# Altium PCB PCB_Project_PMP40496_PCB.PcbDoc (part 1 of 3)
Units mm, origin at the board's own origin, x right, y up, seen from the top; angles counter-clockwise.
Board outline 140 x 100 mm, 4 copper layers (Top Layer, Signal Layer 1, Signal Layer 2, Bottom Layer), stack 1.565 mm thick; 186 components, 128 nets, 605 pads, 270 vias.
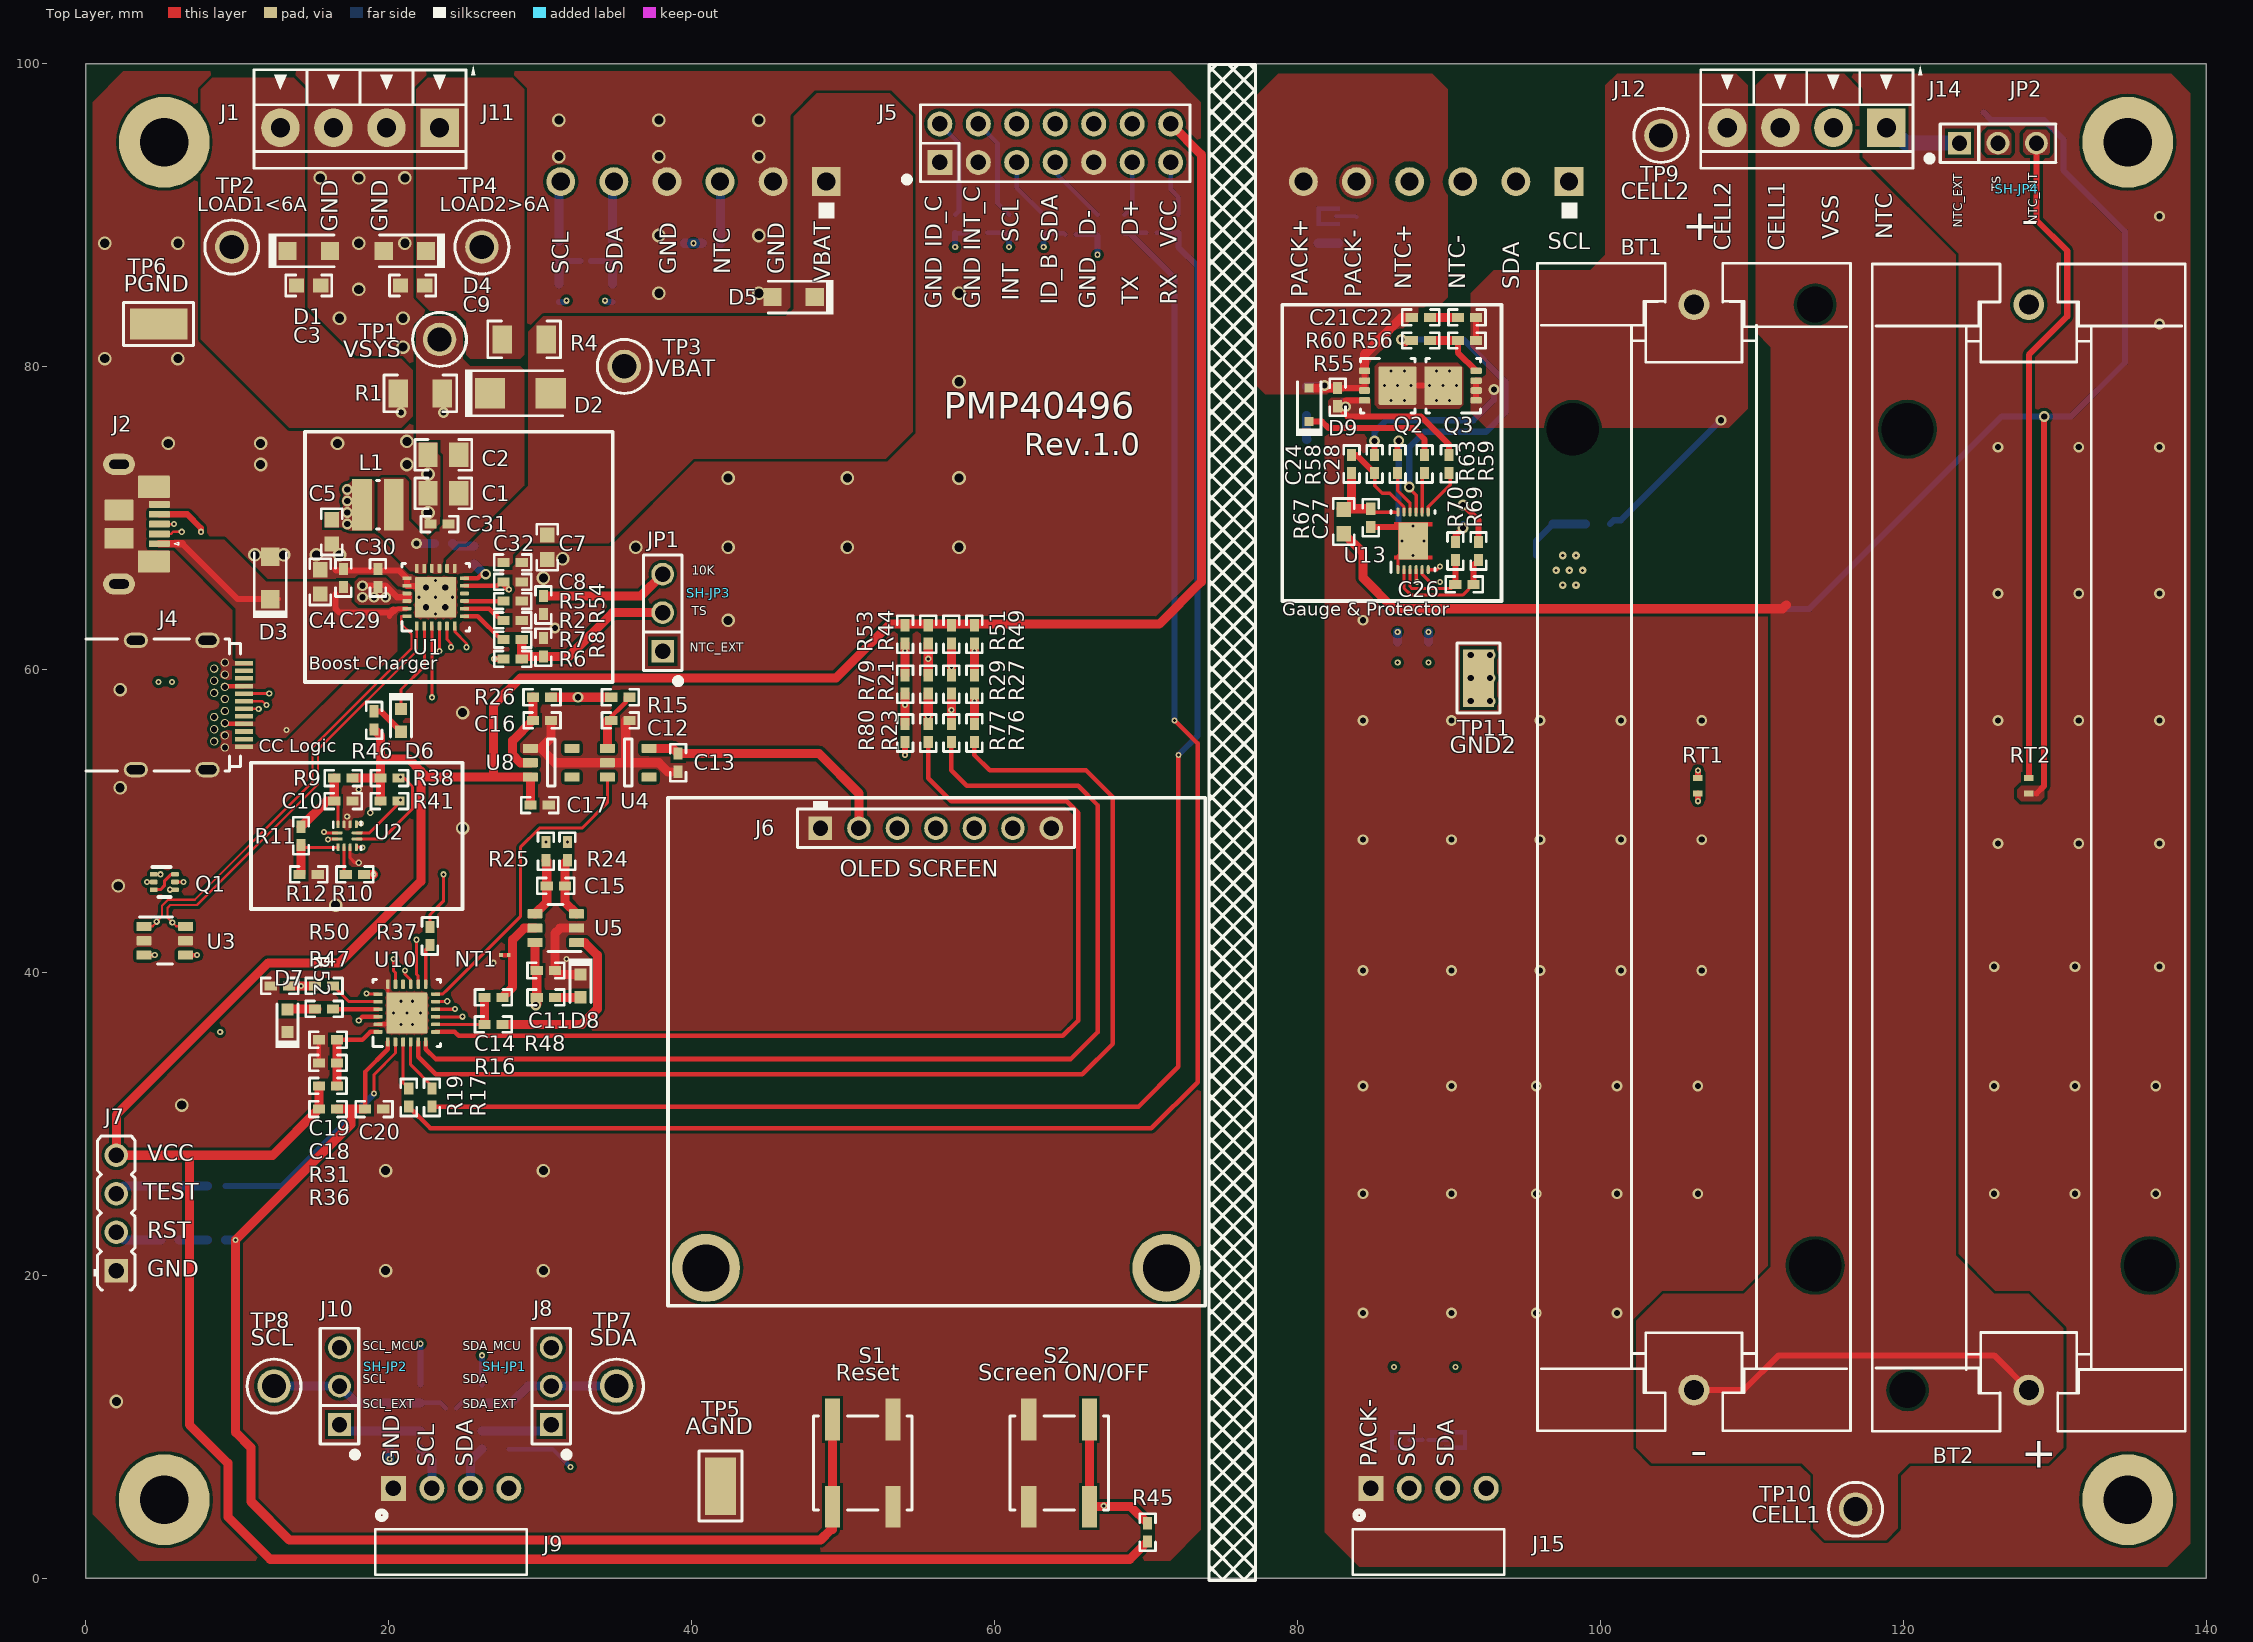
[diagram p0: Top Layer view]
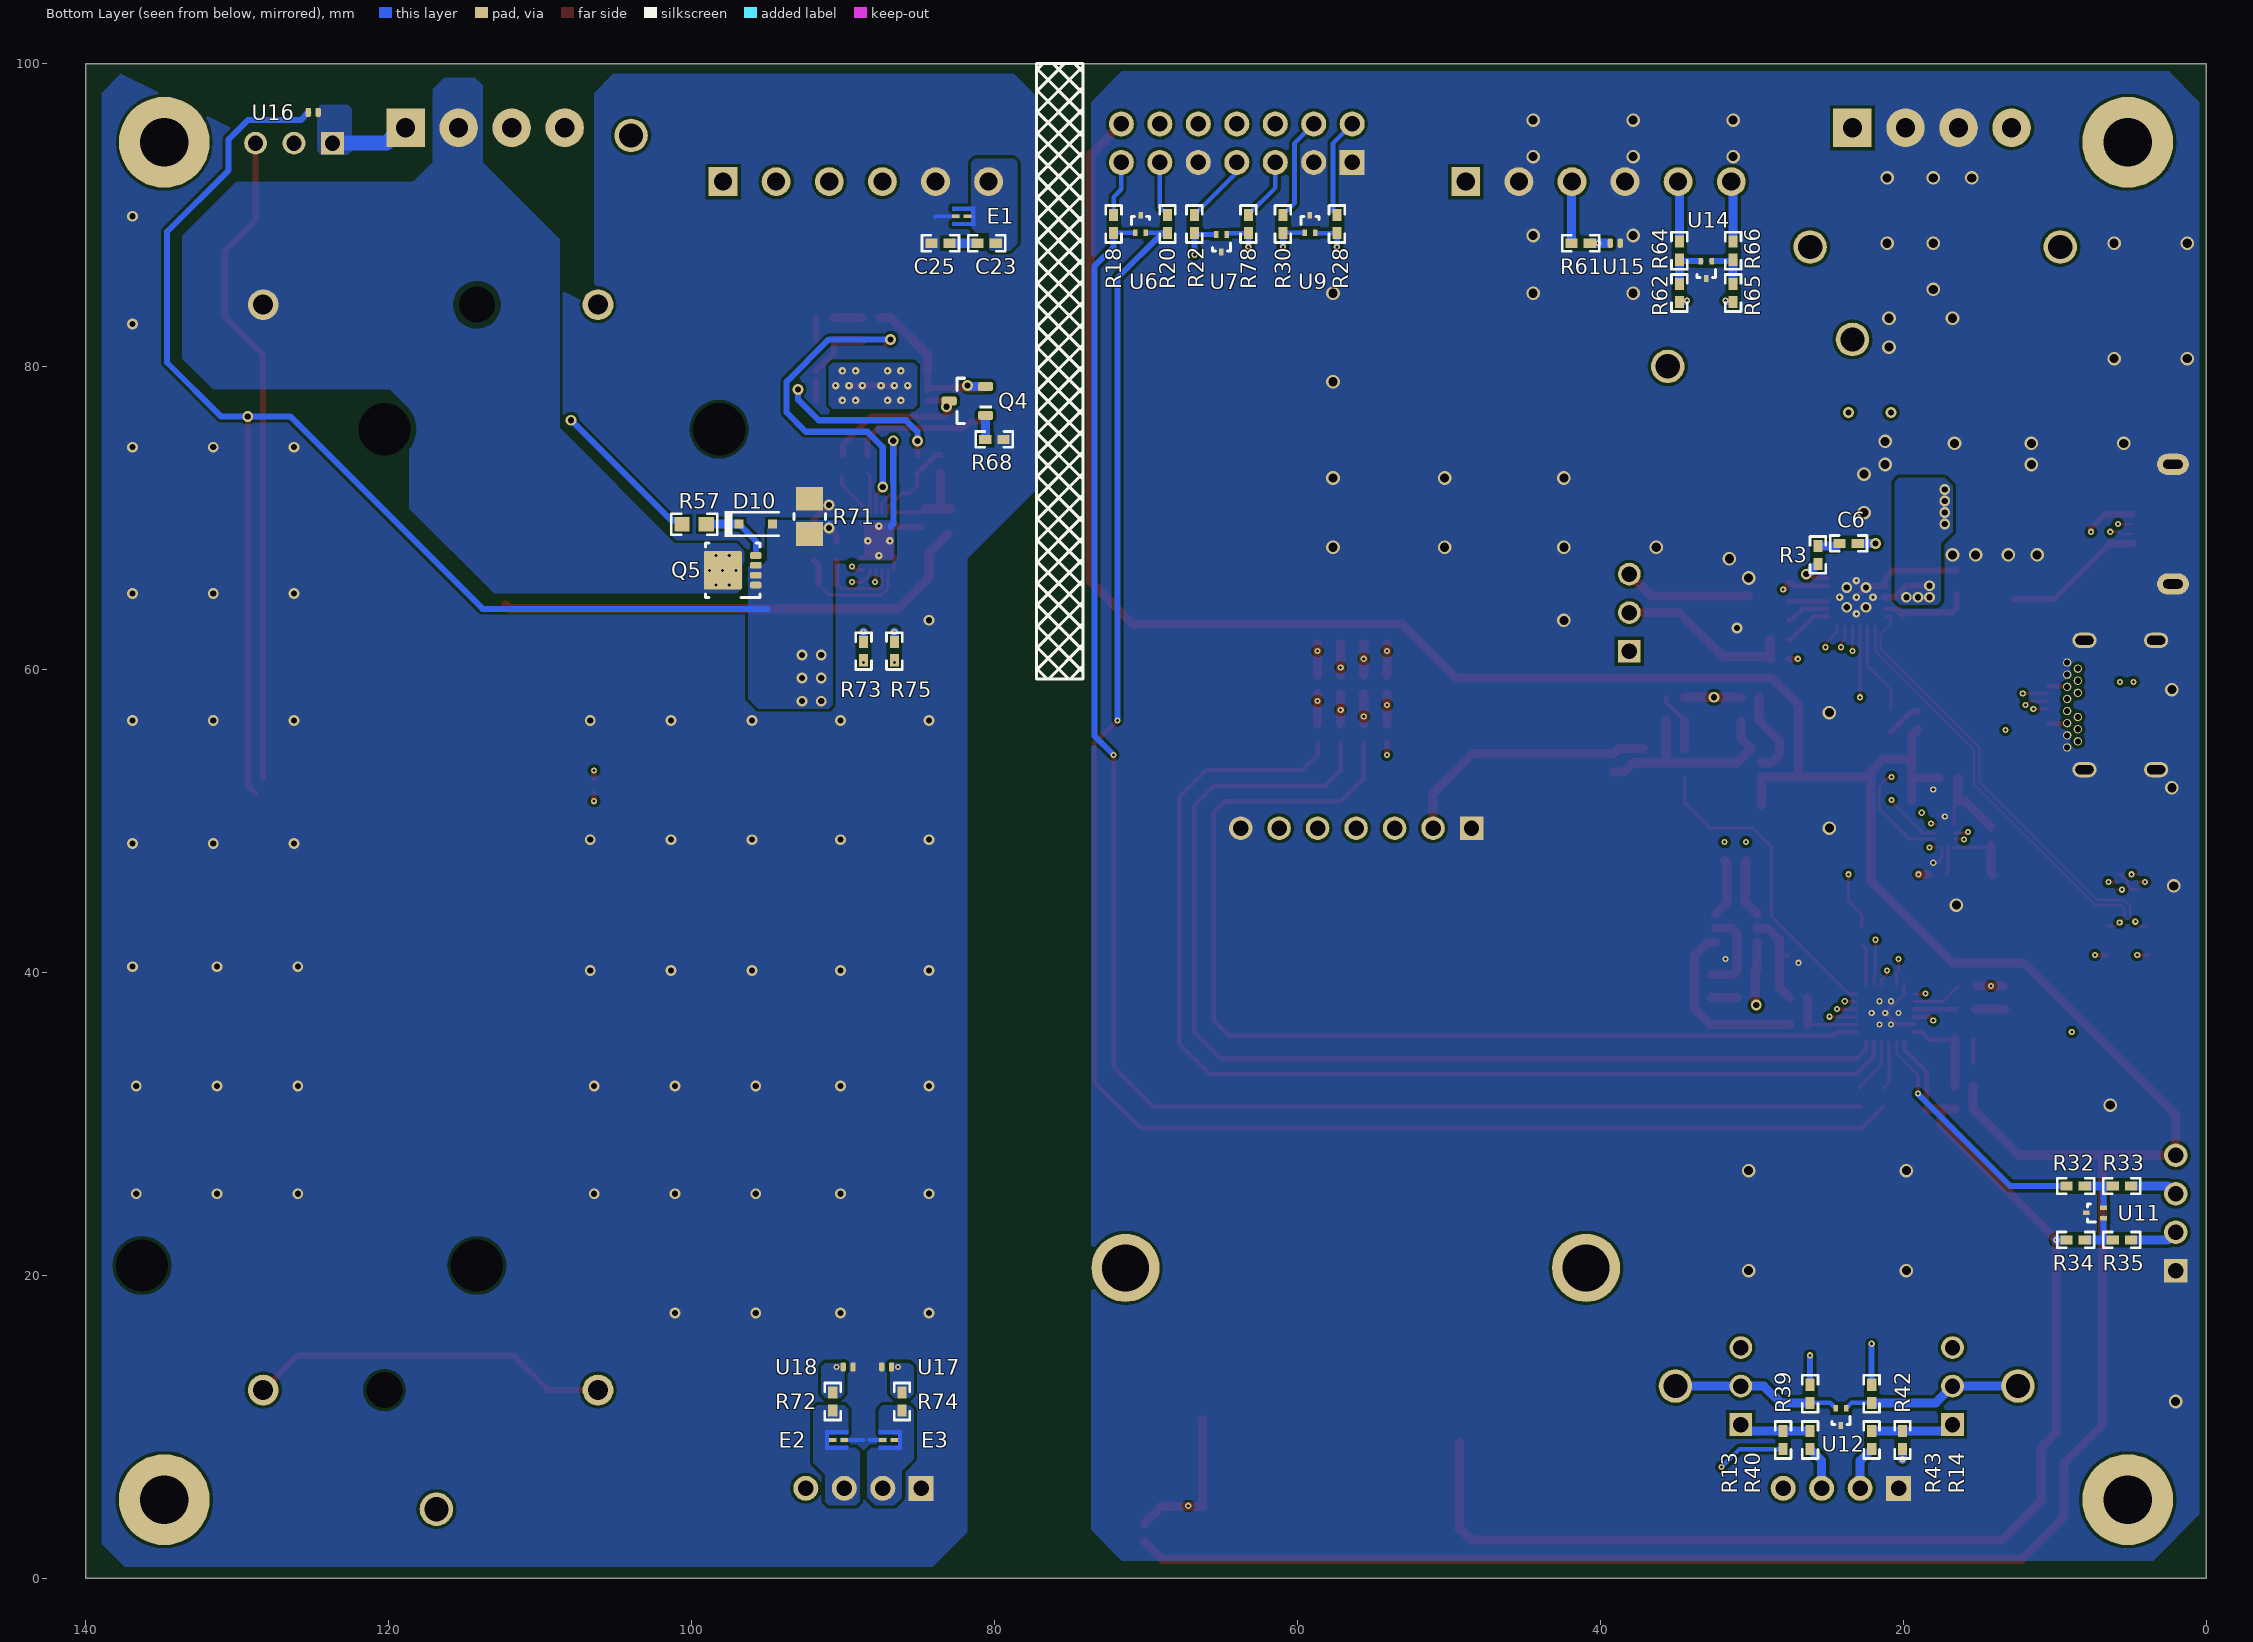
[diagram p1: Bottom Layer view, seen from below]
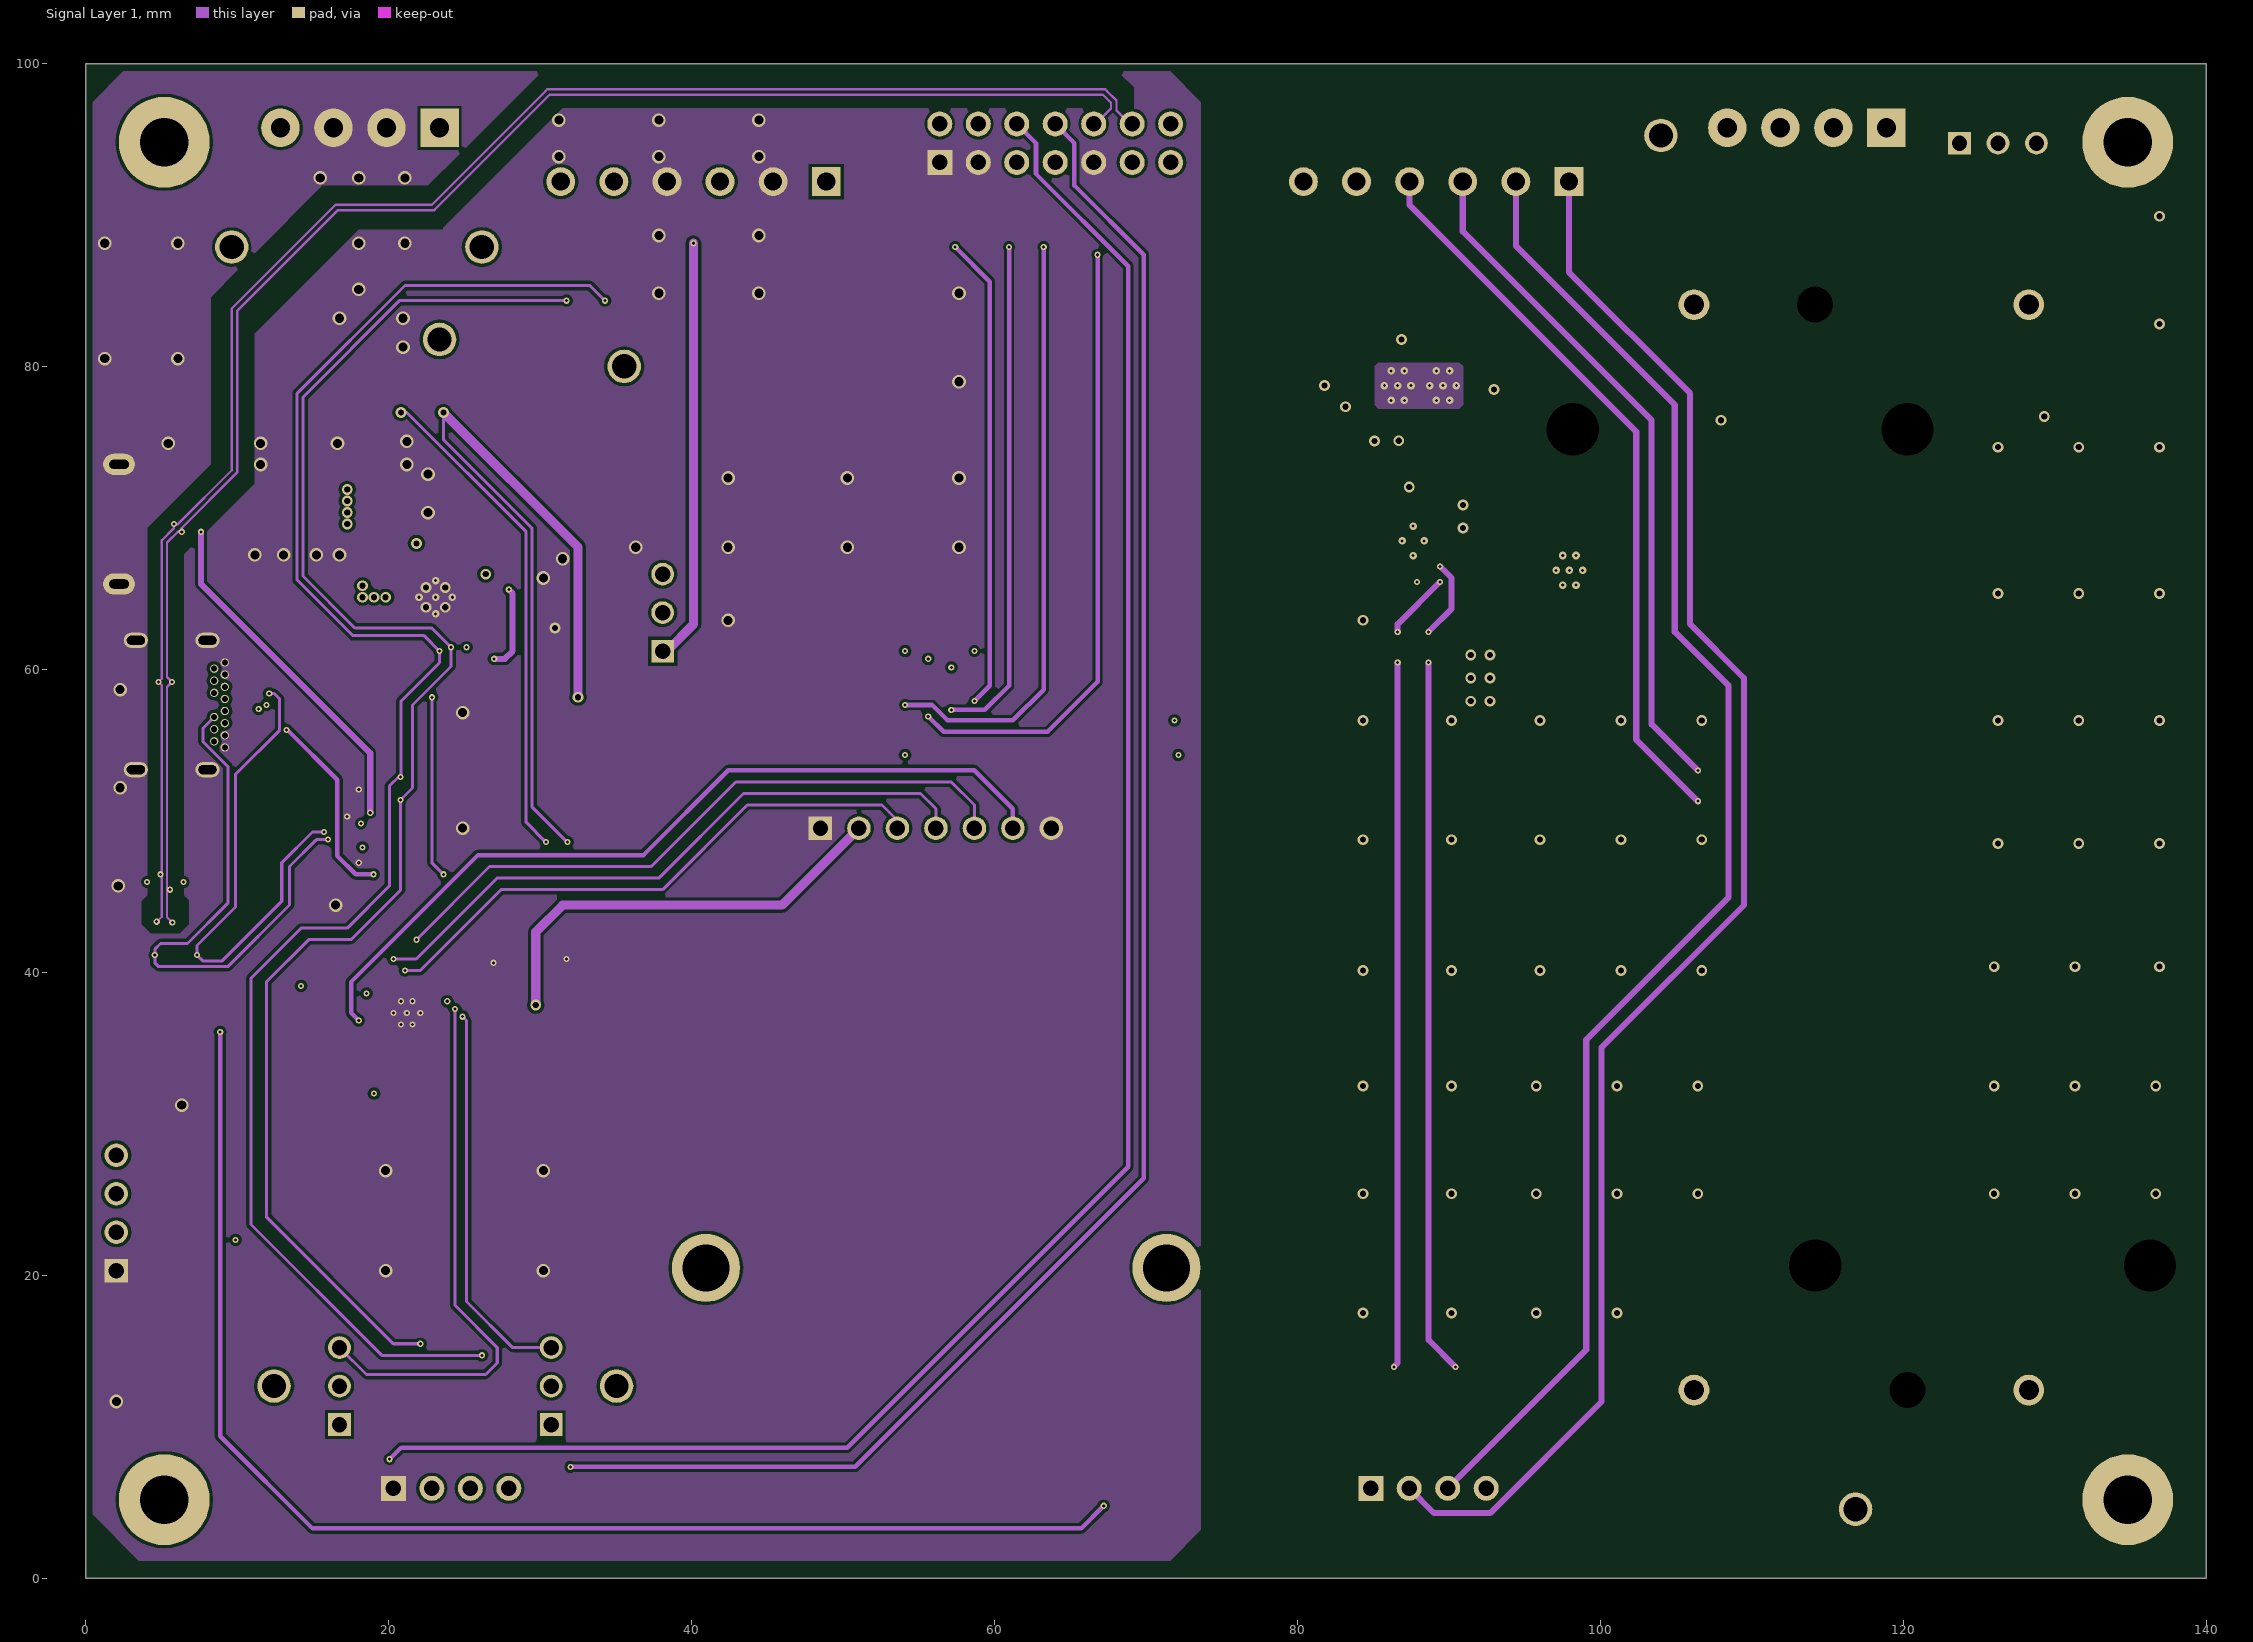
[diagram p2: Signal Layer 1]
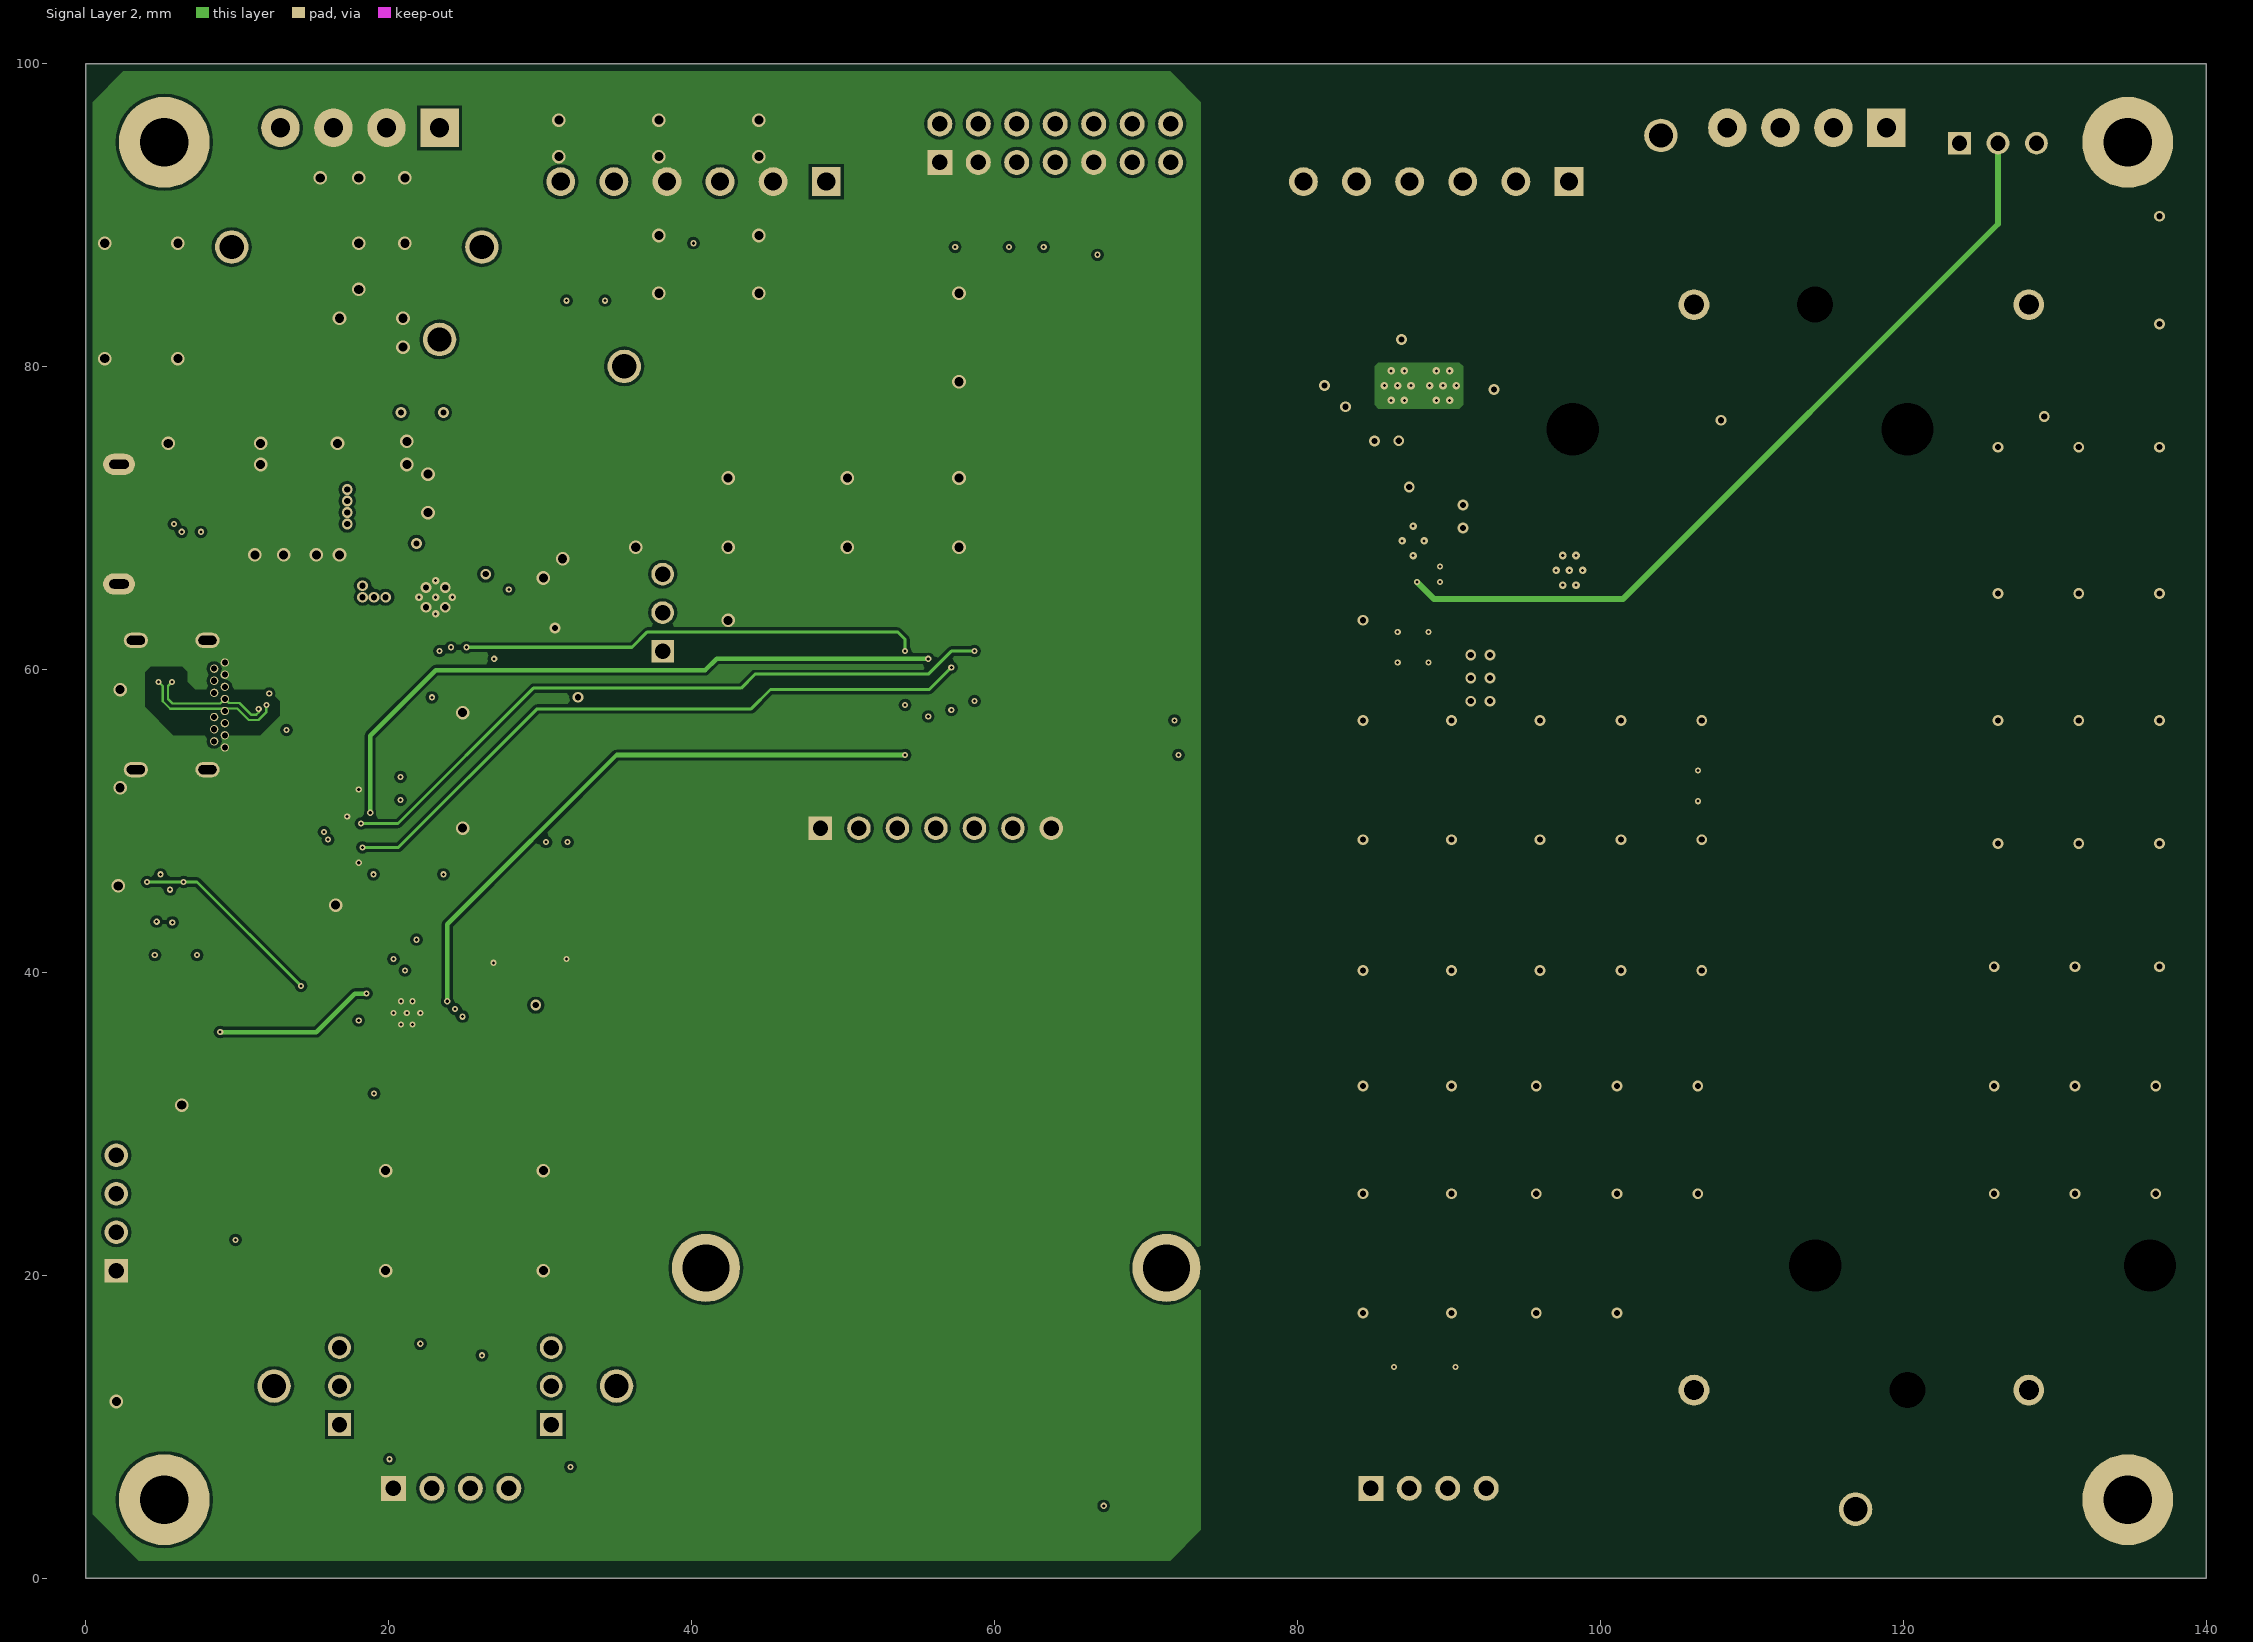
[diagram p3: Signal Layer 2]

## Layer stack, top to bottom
Top Solder: solder mask 0.0102, Solder Resist, Dk 3.5
Top Layer: signal copper 0.0356
Dielectric 1: prepreg 0.2032, FR-4, Dk 4.2
Signal Layer 1: signal copper 0.0356
Dielectric 2: core 1.016, FR-4, Dk 4.2
Signal Layer 2: signal copper 0.0356
Dielectric 3: prepreg 0.2032, FR-4, Dk 4.2
Bottom Layer: signal copper 0.0356
Bottom Solder: solder mask 0.0102, Solder Resist, Dk 3.5

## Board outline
0,0 140,0 140,100 0,100

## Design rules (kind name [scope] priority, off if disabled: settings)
AcuteAngle [All] p1: minimum=4.50000000000000E+0001 checktracksonly=FALSE
AssemblyTestPointUsage [All] p1: valid=2
Clearance Clearance_BoardEdge_MountingHoles [OnCopper and InComponentClass('Mounting Holes') vs IsKeepOut] p1: gap=1.016 ignorepadtopadclearanceinfootprint=FALSE except(0: Arc-Hole Track-Hole SMDPad-Hole THPad-Hole Via-Hole Fill-Hole Poly-Hole Region-Hole Text-Hole)
Clearance Clearance_BoardEdge_Poly [OnCopper and InPoly vs IsKeepOut] p2: gap=0.635 ignorepadtopadclearanceinfootprint=FALSE except(0: Arc-Hole Track-Hole SMDPad-Hole THPad-Hole Via-Hole Fill-Hole Poly-Hole Region-Hole Text-Hole)
Clearance Clearance_BoardEdge [OnCopper and Not InComponentClass('Logo') and not InComponentClass('FiducialMark') and not InRegion(1000,500,4000,800) and Not IsKeepout vs IsKeepOut] p3: gap=0.127 ignorepadtopadclearanceinfootprint=FALSE except(0: Arc-Hole Track-Hole SMDPad-Hole THPad-Hole Via-Hole Fill-Hole Poly-Hole Region-Hole Text-Hole)
Clearance Clearance_Poly [InPolygon] p4: gap=0.2 ignorepadtopadclearanceinfootprint=FALSE
Clearance [All] p5: gap=0.15 ignorepadtopadclearanceinfootprint=FALSE
ComponentClearance ComponentClearance_Logo [All] p1: gap=0.254 collisioncheckmode=3 verticalgap=0.254 showdistances=TRUE
ComponentClearance ComponentClearance_ScrewToNut [(HasFootprint('NY PMS 440 0025 PH')) vs (HasFootprint('Keystone_1902C'))] p2: gap=0.127 collisioncheckmode=3 verticalgap=0.254 showdistances=FALSE
ComponentClearance ComponentClearance_MountingHoles [InComponentClass('Mounting Holes')] p3: gap=0.254 collisioncheckmode=3 verticalgap=2540 showdistances=FALSE
ComponentClearance ComponentClearance_SmallPassives [HasFootprint('0201*') or HasFootprint('0402*') or HasFootprint('0508') or HasFootprint('0603*') or HasFootprint('0612') or HasFootprint('0805*') or HasFootprint('0815*') or HasFootprint('0830*') or HasFootprint('1206*') or HasFootprint('1210*') or HasFootprint('1808*') or HasFootprint('1812*') or HasFootprint('1825*') or HasFootprint('2010*') or HasFootprint('2220*') or HasFootprint('2225*') or HasFootprint('2512*') or HasFootprint('2728*') or HasFootprint('3518*') vs HasFootprint('0201*') or HasFootprint('0402*') or HasFootprint('0508') or HasFootprint('0603*') or HasFootprint('0612') or HasFootprint('0805*') or HasFootprint('0815*') or HasFootprint('0830*') or HasFootprint('1206*') or HasFootprint('1210*') or HasFootprint('1808*') or HasFootprint('1812*') or HasFootprint('1825*') or HasFootprint('2010*') or HasFootprint('2220*') or HasFootprint('2225*') or HasFootprint('2512*') or HasFootprint('2728*') or HasFootprint('3518*')] p4: gap=0.254 collisioncheckmode=3 verticalgap=0.254 showdistances=FALSE
ComponentClearance ComponentClearance_THtoSMT [IsThruComponent vs IsSMTComponent] p5: gap=0.254 collisioncheckmode=3 verticalgap=2540 showdistances=FALSE
ComponentClearance ComponentClearance_THtoTH [IsThruComponent vs IsThruComponent] p6: gap=0.254 collisioncheckmode=3 verticalgap=2540 showdistances=FALSE
ComponentClearance [All] p7: gap=0.254 collisioncheckmode=3 verticalgap=0.254 showdistances=FALSE
DiffPairsRouting DiffPair_90OMDiffPairsRouting [InDifferentialPair ('DATA')] p1: maxlimit=0.203 minlimit=0.203 mostfreqgap=0.203 toplayer_minwidth=0.152 toplayer_maxwidth=0.152 toplayer_prefwidth=0.152 midlayer1_minwidth=0.152 midlayer1_maxwidth=0.152 midlayer1_prefwidth=0.152 midlayer2_minwidth=0.152 midlayer2_maxwidth=0.152 midlayer2_prefwidth=0.152 bottomlayer_minwidth=0.152 bottomlayer_maxwidth=0.152 bottomlayer_prefwidth=0.152 maxuncoupledlength=25.4
DiffPairsRouting [All] p2: maxlimit=0.203 minlimit=0.203 mostfreqgap=0.203 toplayer_minwidth=0.152 toplayer_maxwidth=0.152 toplayer_prefwidth=0.152 midlayer1_minwidth=0.152 midlayer1_maxwidth=0.152 midlayer1_prefwidth=0.152 midlayer2_minwidth=0.152 midlayer2_maxwidth=0.152 midlayer2_prefwidth=0.152 bottomlayer_minwidth=0.152 bottomlayer_maxwidth=0.152 bottomlayer_prefwidth=0.152 maxuncoupledlength=25.4
FabricationTestPointUsage TestPointUsage [All] p1: valid=2 allowmultiple=FALSE
FabricationTestpoint Testpoint [All] p1: side=3 testpointundercomponent=TRUE minsize=1.016 maxsize=2.54 preferedsize=1.524 minholesize=0 maxholesize=1.016 preferedholesize=0.813 testpointgrid=0.025 allowsidetop=TRUE allowsidebottom=TRUE usegrid=TRUE gridtolerance=0
FanoutControl Fanout_LCC [IsLCC] p1: bgadir=Out bgaviamode=Centered fanoutstyle=Auto fanoutdirection=Alternating viagrid=0.025 // Fanout_LCC (Default Rule)
FanoutControl Fanout_BGA [IsBGA] p2: bgadir=Out bgaviamode=Centered fanoutstyle=Auto fanoutdirection=Alternating viagrid=0.025 // Fanout_BGA (Default Rule)
FanoutControl Fanout_Default [All] p4: bgadir=Out bgaviamode=Centered fanoutstyle=Auto fanoutdirection=Alternating viagrid=0.025 // Fanout_Default (Default Rule)
FanoutControl Fanout_Small [(CompPinCount < 5)] p5: bgadir=Out bgaviamode=Centered fanoutstyle=Auto fanoutdirection=OutThenIn viagrid=0.025 // Fanout_Small (Default Rule)
HoleSize [All] p1: absolutevalues=TRUE maxlimit=6.375 minlimit=0.152 maxpercent=80.000 minpercent=20.000
MatchedLengths DiffPair_90OMMatchedLengths [InDifferentialPair ('DATA')] p1: tolerance=25.4 checknetsindiffpair=FALSE checkdiffpairvsdiffpair=TRUE checkxsignals=TRUE checkothers=TRUE
MinimumAnnularRing [All] p1: minimumring=0.074
MinimumSolderMaskSliver MinimumSolderMaskSliver_Logo [InComponentClass('Logo') vs InComponentClass('Logo')] p1: minsoldermaskwidth=0.018
MinimumSolderMaskSliver [All] p2: minsoldermaskwidth=0
PlaneConnect [All] p1: planeconnectstyle=Direct reliefexpansion=0.254 reliefentries=4 reliefconductorwidth=0.254 reliefairgap=0.254
PolygonConnect [All] p1: connectstyle=Direct reliefconductorwidth=0.254 reliefentries=4 polygonreliefangle="90 Angle" airgapwidth=0.254
RoutingCorners [All] p1: cornerstyle=45-Degree minsetback=0.254 maxsetback=2.54
RoutingVias [All] p1: holewidth=0.406 width=0.864 viastyle="Through Hole" minholewidth=0.2 minwidth=0.406 maxholewidth=1.016 maxwidth=1.651
SMDToCorner [All] p1: distance=0
SilkToBoardRegionClearance [Not ((IsComment or IsDesignator) And (Hide <> 'False')) and not InRegion(1000,500,4000,800)] p1:
SilkToSilkClearance [All] p1: silktosilkclearance=0
SilkToSolderMaskClearance SilkscreenOverComponentPads [IsPad] p1: minsilkscreentomaskgap=0 clearancetoexposedcopper=TRUE
SolderMaskExpansion [All] p1: expansion=0.076
Width [All] p1: maxlimit=2.54 minlimit=0.152 preferedwidth=0.254 checkconnectedcopper=TRUE
14 further rules are at their usual default settings.

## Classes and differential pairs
component class Shunt: SH-JP1 SH-JP2 SH-JP3 SH-JP4
component class PCB_Project_PMP40496_BatteryPack: BT1 BT2 C21 C22 C23 C24 C25 C26 C27 C28 D9 D10 E1 E2 E3 J11 J12 J14 J15 JP1 JP2 Q2 Q3 Q4 Q5 R54 R55 R56 R57 R58 R59 R60 R61 R62 R63 R64 R65 R66 R67 R68 R69 R70 R71 R72 R73 R74 R75 RT1 RT2 SH-JP3 SH-JP4 TP9 TP10 TP11 U13 U14 U15 U16 U17 U18
component class Header: J5 J7 J8 J10 JP1 JP2
component class PCB_Project_PMP40496_BlankSheet: C1 C2 C3 C4 C5 C6 C7 C8 C9 C10 C29 C30 C31 C32 D1 D2 D3 D4 D5 J1 J2 J4 L1 R1 R2 R3 R4 R5 R6 R7 R8 R9 R10 R11 R12 TP1 TP2 TP3 TP4 TP5 TP6 U1 U2 U3
component class PCB_Project_PMP40496_EVM_Hardware: C11 C12 C13 C14 C15 C16 C17 C18 C19 C20 D6 D7 D8 J5 J6 J7 J8 J9 J10 NT1 Q1 R13 R14 R15 R16 R17 R18 R19 R20 R21 R22 R23 R24 R25 R26 R27 R28 R29 R30 R31 R32 R33 R34 R35 R36 R37 R38 R39 R40 R41 R42 R43 R44 R45 R46 R47 R48 R49 R50 R51 R52 R53 R76 R77 R78 R79 R80 S1 S2 SH-JP1 SH-JP2 TP7 TP8 U4 U5 U6 U7 U8 U9 U10 U11 U12
differential pair DATA: +DATA_P -DATA_N

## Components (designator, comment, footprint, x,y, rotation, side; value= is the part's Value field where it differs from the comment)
BT1 "1043" BAT_1043 106.172,48.26 r270 top locked
BT2 "1043" BAT_1043 128.27,48.26 r90 top locked
C1 "GRM21BR61E226ME44L" 0805_HV 23.622,71.628 r180 top value=22uF
C2 "GRM21BR61E226ME44L" 0805_HV 23.622,74.168 r180 top value=22uF
C3 "CGJ3E1X7R1E105K080AC" 0603 14.732,85.344 r0 top value=1uF
C4 "C1608X5R1E106M080AC" 0603 15.494,65.786 r90 top value=10uF
C5 "C1608X5R1E106M080AC" 0603 16.256,69.088 r270 top value=10uF
C6 "GRM155R71E473KA88D" 0402 23.622,68.326 r180 bottom value=0.047uF
C7 "C1608X5R1E106M080AC" 0603 30.48,68.072 r270 top value=10uF
C8 "C1005X5R1A475K050BC" 0402_065 28.194,65.786 r0 top value=4.7uF
C9 "CGJ3E1X7R1E105K080AC" 0603 21.59,85.344 r180 top value=1uF
C10 "EMK105BJ105KVHF" 0402 17.018,51.308 r0 top value=1uF
C11 "GRM155R71E104KE14D" 0402 30.388,40.132 r0 top value=0.1uF
C12 "EMK105BJ105KVHF" 0402 35.306,56.642 r0 top value=1uF
C13 "C1005X5R1A475K050BC" 0402_065 39.12,53.848 r270 top value=4.7uF
C14 "GRM155R71E103KA01D" 0402 26.924,38.354 r0 top value=0.01uF
C15 "GRM155R71E104KE14D" 0402 31.045,45.72 r180 top value=0.1uF
C16 "GRM155R71E104KE14D" 0402 30.138,56.642 r0 top value=0.1uF
C17 "EMK105BJ105KVHF" 0402 29.976,51.054 r0 top value=1uF
C18 "C1005X5R1A475K050BC" 0402_065 16.002,34.036 r180 top value=4.7uF
C19 "GRM155R71E104KE14D" 0402 16.002,35.56 r180 top value=0.1uF
C20 "GRM155R61E102KA01D" 0402 19.05,30.988 r0 top value=1000pF
C21 "C1005X7R1H104K050BB" 0402 88.141,83.241 r180 top value=0.1uF
C22 "C1005X7R1H104K050BB" 0402 91.189,83.241 r180 top value=0.1uF
C23 "C1005X7R1H104K050BB" 0402 80.518,88.138 r0 bottom value=0.1uF
C24 "EMK105BJ105KVHF" 0402 83.566,73.568 r270 top value=1uF
C25 "C1005X7R1H104K050BB" 0402 83.566,88.138 r0 bottom value=0.1uF
C26 "GRM155R71E104KE14D" 0402 91.013,65.613 r180 top value=0.1uF
C27 "GRM155R71E104KE14D" 0402 84.836,70.012 r270 top value=0.1uF
C28 "GRM155R61C225KE11D" 0402 86.614,73.568 r90 top value=2.2uF
C29 "GRM155R71E103KA01D" 0402 17.018,66.04 r90 top value=0.01uF
C30 "GRM155R71E103KA01D" 0402 19.304,66.04 r90 top value=0.01uF
C31 "GRM155R71E103KA01D" 0402 23.368,69.596 r180 top value=0.01uF
C32 "GRM155R71E103KA01D" 0402 28.194,67.066 r0 top value=0.01uF
D1 "PTVS13VS1UR,115" SOD-123W 14.732,87.63 r0 top value=13V
D2 "B320A-13-F" SMA 28.702,78.232 r0 top value=20V
D3 "PTVS13VS1UR,115" SOD-123W 12.192,66.04 r90 top value=13V
D4 "PTVS13VS1UR,115" SOD-123W 21.082,87.63 r180 top value=13V
D5 "PTVS13VS1UR,115" SOD-123W 46.736,84.582 r180 top value=13V
D6 "LTST-C190GKT" LED_LTST-C190 20.828,56.642 r90 top value=Green
D7 "LTST-C190CKT" LED_LTST-C190_Red 13.335,36.817 r270 top value=Red
D8 "LTST-C190KFKT" LED_LTST-C190 32.674,39.116 r90 top value=Orange
D9 "1N4148WX-TP" SOD-323 80.772,77.47 r90 top value=75V
D10 "MMSZ5245BS-7-F" SOD-323 95.758,69.596 r180 bottom value=15V
E1 "N/A" SPARK_GAP2 82.042,89.916 r90 bottom
E2 "N/A" SPARK_GAP2 90.424,9.144 r270 bottom
E3 "N/A" SPARK_GAP2 86.868,9.144 r90 bottom
J1 "ED555/4DS" TERM_BLK_ED555-4DS 23.368,95.758 r180 top
J2 "1051640001" Molex_1051640001 0.762,69.596 r270 top locked
J4 "632723300011" Wurth_632_723_300_011 -0.127,57.658 r270 top locked
J5 "PEC07DAAN" CONN_PEC07DAAN 64.008,94.742 r0 top
J6 "PPPC071LFBN-RC" Sullins_xPxC071LFBN 56.134,49.53 r0 top
J7 "22284043" Molex_0022284043 2.032,24.13 r90 top
J8 "PEC03SAAN" CONN_PEC03SAAN 30.734,12.7 r90 top
J9 "22/05/3041" CONN_22-05-3041 24.13,0.254 r0 top
J10 "PEC03SAAN" CONN_PEC03SAAN 16.764,12.7 r90 top
J11 "395021006" HEADER_395021006 40.132,92.202 r180 top
J12 "395021006" HEADER_395021006 89.154,92.202 r180 top
J14 "ED555/4DS" TERM_BLK_ED555-4DS 118.872,95.758 r180 top
J15 "22/05/3041" CONN_22-05-3041 88.646,0.254 r0 top
JP1 "PEC03SAAN" CONN_PEC03SAAN 38.1,63.754 r90 top
JP2 "PEC03SAAN" CONN_PEC03SAAN 126.238,94.742 r0 top
L1 "74438336100" WE-MAPI_3020 19.304,70.866 r0 top
NT1 "Net-Tie" Net-Tie_10mil 27.686,41.148 r0 top net-tie
Q1 "NTZD3154NT1G" SOT-563 5.207,45.974 r0 top value=20V
Q2 "CSD16327Q3" DQG0008A#1 85.95,78.74 r0 top value=25V
Q3 "CSD16327Q3" DQG0008A#1 90.268,78.74 r180 top value=25V
Q4 "2N7002K-T1-E3" SOT-23 81.788,77.724 r0 bottom value=60V
Q5 "CSD16327Q3" DQG0008A#2 97.282,66.548 r0 bottom value=25V
R1 "CSR1206FK10L0" 1206 22.098,78.232 r180 top value=0.01
R2 "CRCW0402392RFKED" 0402 28.194,63.246 r180 top value=392
R3 "CRCW04020000Z0ED" 0402 25.654,67.564 r270 bottom value=0
R4 "CSR1206FK10L0" 1206 28.956,81.788 r0 top value=0.01
R5 "ERJ-2GEJ103X" 0402 28.194,64.516 r180 top value=10k
R6 "CRCW04025K23FKED" 0402 28.194,60.706 r180 top value=5.23k
R7 "RC0402FR-07100RL" 0402 28.194,61.976 r180 top value=100
R8 "RC0402FR-0730K1L" 0402 30.226,61.468 r270 top value=30.1k
R9 "CRCW04021R00FKED" 0402 17.018,52.832 r0 top value=1.00
R10 "CRCW0402909KFKED" 0402 17.78,46.482 r180 top value=909k
R11 "ERJ-2GEJ103X" 0402 14.224,49.022 r270 top value=10k
R12 "ERJ-2GEJ103X" 0402 14.732,46.482 r0 top value=10k
R13 "RC0402FR-07100RL" 0402 27.94,9.144 r270 bottom value=100
R14 "RC0402FR-07100RL" 0402 20.066,9.144 r90 bottom value=100
R15 "CRCW04021R00FKED" 0402 35.306,58.166 r0 top value=1.00
R16 "RC0402FR-07100RL" 0402 26.924,36.576 r0 top value=100
R17 "RC0402FR-07100RL" 0402 22.86,31.75 r90 top value=100
R18 "RC0402FR-07100RL" 0402 72.136,89.408 r270 bottom value=100
R19 "RC0402FR-07100RL" 0402 21.336,31.75 r90 top value=100
R20 "RC0402FR-07100RL" 0402 68.58,89.408 r270 bottom value=100
R21 "RC0402FR-07100RL" 0402 55.626,59.02 r90 top value=100
R22 "RC0402FR-07100RL" 0402 66.802,89.408 r270 bottom value=100
R23 "RC0402FR-07100RL" 0402 55.626,55.81 r270 top value=100
R24 "MCR01MZPF10R0" 0402 31.807,48.006 r270 top value=10.0
R25 "MCR01MZPF10R0" 0402 30.388,48.006 r270 top value=10.0
R26 "CRCW04021R00FKED" 0402 30.134,58.166 r180 top value=1.00
R27 "RC0402FR-07100RL" 0402 58.674,59.02 r90 top value=100
R28 "RC0402FR-07100RL" 0402 57.404,89.408 r270 bottom value=100
R29 "RC0402FR-07100RL" 0402 57.15,59.02 r90 top value=100
R30 "RC0402FR-07100RL" 0402 60.96,89.408 r270 bottom value=100
R31 "CRCW04021R00FKED" 0402 16.002,32.512 r180 top value=1.00
R32 "RC0402FR-07100RL" 0402 8.636,25.908 r0 bottom value=100
R33 "RC0402FR-07100RL" 0402 5.588,25.908 r0 bottom value=100
R34 "RC0402FR-07100RL" 0402 8.636,22.352 r0 bottom value=100
R35 "RC0402FR-07100RL" 0402 5.588,22.352 r0 bottom value=100
R36 "RC0402FR-0747KL" 0402 16.002,30.988 r180 top value=47.0k
R37 "RC0402FR-07100RL" 0402 22.733,42.405 r90 top value=100
R38 "ERJ-2GEJ103X" 0402 20.066,52.832 r180 top value=10k
R39 "RC0402FR-07100RL" 0402 26.162,12.192 r90 bottom value=100
R40 "RC0402FR-07100RL" 0402 26.162,9.144 r90 bottom value=100
R41 "ERJ-2GEJ103X" 0402 20.066,51.308 r180 top value=10k
R42 "RC0402FR-07100RL" 0402 22.098,12.192 r90 bottom value=100
R43 "RC0402FR-07100RL" 0402 22.098,9.144 r90 bottom value=100
R44 "ERJ-2GEJ103X" 0402 55.626,62.322 r90 top value=10k
R45 "RC0402FR-0747KL" 0402 70.104,3.048 r270 top value=47.0k
R46 "ERJ-2RKF1501X" 0402 19.05,56.642 r270 top value=1.50k
R47 "ERJ-2RKF1501X" 0402 15.748,37.592 r0 top value=1.50k
R48 "ERJ-2RKF1501X" 0402 30.388,38.354 r180 top value=1.50k
R49 "ERJ-2GEJ103X" 0402 58.674,62.322 r90 top value=10k
R50 "CRCW04021K00JNED" 0402 15.748,39.116 r0 top value=1.0k
R51 "ERJ-2GEJ103X" 0402 57.15,62.322 r90 top value=10k
R52 "CRCW0402100KJNED" 0402 12.827,39.116 r0 top value=100k
R53 "ERJ-2GEJ103X" 0402 54.102,62.322 r90 top value=10k
R54 "ERJ-2GEJ103X" 0402 30.226,64.262 r90 top value=10k
R55 "CRCW040210M0JNED" 0402 82.648,77.978 r90 top value=10Meg
R56 "CRCW040210M0JNED" 0402 91.189,81.717 r0 top value=10Meg
R57 "RC0603JR-071KL" 0603 99.822,69.596 r0 bottom value=1.0k
R58 "CRCW04024R99FKED" 0402 85.09,73.568 r90 top value=4.99
R59 "CRCW04025K10JNED" 0402 89.987,73.571 r90 top value=5.1k
R60 "CRCW04025K10JNED" 0402 88.141,81.717 r0 top value=5.1k
R61 "RC0402FR-07100RL" 0402 41.31,88.138 r180 bottom value=100
R62 "RC0402FR-07100RL" 0402 34.798,84.854 r270 bottom value=100
R63 "MCR01MZPF10R0" 0402 88.392,73.568 r90 top value=10.0
R64 "RC0402FR-07100RL" 0402 34.798,87.648 r270 bottom value=100
R65 "RC0402FR-07100RL" 0402 31.242,84.854 r270 bottom value=100
R66 "RC0402FR-07100RL" 0402 31.242,87.648 r270 bottom value=100
R67 "CRCW0603100RFKEA" 0603 83.058,69.758 r270 top value=100
R68 "ERJ-2GEJ103X" 0402 80.01,75.184 r0 bottom value=10k
R69 "RC0402FR-07100RL" 0402 91.948,67.818 r270 top value=100
R70 "RC0402FR-07100RL" 0402 90.424,67.818 r270 top value=100
R71 "WSLP12061L000FEA" WSLP1206-001 92.202,70.104 r270 bottom value=0.001
R72 "RC0402FR-07100RL" 0402 90.678,11.684 r90 bottom value=100
R73 "RC0402FR-07100RL" 0402 88.646,61.214 r90 bottom value=100
R74 "RC0402FR-07100RL" 0402 86.106,11.684 r90 bottom value=100
R75 "RC0402FR-07100RL" 0402 86.614,61.214 r90 bottom value=100
R76 "RC0402FR-07100RL" 0402 58.674,55.81 r270 top value=100
R77 "RC0402FR-07100RL" 0402 57.15,55.81 r270 top value=100
R78 "RC0402FR-07100RL" 0402 63.246,89.408 r270 bottom value=100
R79 "RC0402FR-07100RL" 0402 54.102,59.02 r90 top value=100
R80 "RC0402FR-07100RL" 0402 54.102,55.81 r270 top value=100
RT1 "NCP15XH103F03RC" 0402S 106.426,52.324 r270 top value=10k
RT2 "NCP15XH103F03RC" 0402S 128.27,52.324 r90 top value=10k
S1 "B3SL-1002P" SW_B3SL-1002P 51.308,7.62 r270 top
S2 "B3SL-1002P" SW_B3SL-1002P 64.262,7.62 r90 top
SH-JP1 "969102-0000-DA" SNT-100-BK-G 27.686,13.97 r270 top value=1x2
SH-JP2 "969102-0000-DA" SNT-100-BK-G 19.812,13.97 r270 top value=1x2
SH-JP3 "969102-0000-DA" SNT-100-BK-G 41.148,65.024 r90 top value=1x2
SH-JP4 "969102-0000-DA" SNT-100-BK-G 127.508,91.694 r0 top value=1x2
TP1 "5010" Keystone5010 23.368,81.788 r90 top
TP2 "5010" Keystone5010 9.652,87.884 r90 top
TP3 "5013" Keystone5013 35.56,80.01 r90 top
TP4 "5013" Keystone5013 26.162,87.884 r90 top
TP5 "TESTPOINT" Keystone_5019 41.91,6.096 r90 top
TP6 "TESTPOINT" Keystone_5019 4.826,82.804 r180 top
TP7 "5007" Keystone5007 35.052,12.7 r90 top
TP8 "5008" Keystone5008 12.446,12.7 r90 top
TP9 "5010" Keystone5010 103.987,95.25 r90 top
TP10 "5013" Keystone5013 116.84,4.572 r90 top
TP11 "TESTPOINT" Keystone_5019 91.948,59.436 r90 top
U1 "BQ25881RGER" RGE0024H 23.114,64.77 r90 top
U2 "TUSB320LAIRWBR" RWB0012A 17.272,49.022 r0 top
U3 "TPD4E1U06DBVR" DBV0006A_N 5.229,42.098 r0 top
U4 "TPS70933DBVR" DBV0005A_N 35.822,53.848 r0 top
U5 "INA181A2IDBV" DBV0006A_N 31.045,42.926 r180 top
U6 "TPD2EUSB30ADRTR" DRT0003A 70.358,89.408 r90 bottom
U7 "TPD2EUSB30ADRTR" DRT0003A 65.024,88.138 r270 bottom
U8 "TLV70433DBVR" DBV0005A_N 30.738,53.848 r0 top
U9 "TPD2EUSB30ADRTR" DRT0003A 59.182,89.408 r90 bottom
U10 "MSP430FR2433IRGER" RGE0024H_NV 21.209,37.325 r90 top
U11 "TPD2EUSB30ADRTR" DRT0003A 7.366,24.13 r0 bottom
U12 "TPD2EUSB30ADRTR" DRT0003A 24.13,10.668 r270 bottom
U13 "BQ28Z610DRZR" DRZ0012A 87.63,68.488 r90 top
U14 "TPD2EUSB30ADRTR" DRT0003A 33.02,86.378 r270 bottom
U15 "ESD351DPYR" DPY0002A 39.024,88.138 r180 bottom
U16 "ESD351DPYR" DPY0002A 124.968,96.774 r0 bottom
U17 "ESD351DPYR" DPY0002A 87.122,13.97 r0 bottom
U18 "ESD351DPYR" DPY0002A 89.662,13.97 r180 bottom

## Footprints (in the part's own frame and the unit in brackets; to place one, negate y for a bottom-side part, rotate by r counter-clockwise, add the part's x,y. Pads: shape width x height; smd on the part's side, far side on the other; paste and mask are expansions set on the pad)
0402 [mm] "0402 from SM-752 data"
  rect 0.8x0.6 smd: 1(-0.6,0) 2(0.6,0)
  silkscreen extent -1.22,-0.52 1.22,0.52, body extent -0.55,-0.3 0.55,0.3, height 0.6
0402_065 [mm] "0402"
  rect 0.8x0.6 smd: 1(-0.6,0) 2(0.6,0)
  silkscreen extent -1.22,-0.52 1.22,0.52, body extent -0.55,-0.3 0.55,0.3, height 0.65
0402S [mil] "Based on C0402S footprint from PADS legacy"
  rect 15x24 smd: 1(-20,0) 2(20,0)
  body extent -22,-12 22,12, height 24
0603 [mm] "0603 from SM-752 data"
  rect 1x0.95 smd: 1(-0.8,0) 2(0.8,0)
  silkscreen extent -1.52,-0.69 1.52,0.69, body extent -0.87,-0.47 0.87,0.47, height 1
0805_HV [mil] "0805 with 30mil clearance between pads"
  rect 50x63 smd: 1(-40,0) 2(40,0)
  silkscreen extent -74,-40 74,40, body extent -43,-29 43,29, height 57
1206 [mm] "1206 from SM-752 data"
  rect 1.3x1.85 smd: 1(-1.45,0) 2(1.45,0)
  silkscreen extent -2.4,-1.21 2.4,1.21, body extent -1.7,-0.9 1.7,0.9, height 1.35
BAT_1043 [mil] "Keystone"
  round 80 hole 52: 1(-1410.24,0) 2(1410.24,0)
  round 60 hole 136 unplated: MH1(-1086.61,-314.96) MH2(1086.61,314.96)
  round 60 hole 93.5 unplated: MH3(-1410.24,314.96)
  silkscreen extent -1518,-407 1516,406, body extent -1518,-407 1516,406, height 590
CONN_22-05-3041 [mm] "MOLEX"
  rect 1.65x1.65 hole 1.02: 1(-3.81,5.7)
  round 1.65 hole 1.02: 2(-1.27,5.7) 3(1.27,5.7) 4(3.81,5.7)
  silkscreen extent -5,0 5,4.18, body extent -5,-6.91 5,6.02, height 6.37
CONN_PEC03SAAN [mm] "SULLINS"
  rect 1.5x1.5 hole 1.016: 1(-2.54,0)
  round 1.5 hole 1.016: 2(0,0) 3(2.54,0)
  silkscreen extent -4.72,-1.27 3.81,1.27, body extent -3.84,-1.3 3.84,1.3, height 8.38
CONN_PEC07DAAN [mm] "SULLINS"
  rect 1.65x1.65 hole 1.016 mask+0: 1(-7.62,-1.27)
  round 1.65 hole 1.016 mask+0: 2(-7.62,1.27) 3(-5.08,-1.27) 4(-5.08,1.27) 5(-2.54,-1.27) 6(-2.54,1.27) 7(0,-1.27) 8(0,1.27) 9(2.54,-1.27) 10(2.54,1.27) 11(5.08,-1.27) 12(5.08,1.27) 13(7.62,-1.27) 14(7.62,1.27)
  silkscreen extent -9.99,-2.6 8.89,2.54, body extent -8.95,-2.6 8.95,2.6, height 8.38
DBV0005A_N [mm] "SOT23, 5-Leads, Body 2.9x1.6mm, Pitch 0.95mm, Lead Span 2.8mm, IPC Medium Density"
  rrect17% 1x0.6 smd: 1(-1.375,0.95) 2(-1.375,0) 3(-1.375,-0.95) 4(1.375,-0.95) 5(1.375,0.95)
  silkscreen extent -0.25,-1.55 0.25,1.55, body extent -1.42,-1.46 1.42,1.46, height 1.09
DBV0006A_N [mm] "SOT23, 6-Leads, Body 2.9x1.6mm, Pitch 0.95mm, Lead Span 2.8mm, IPC Medium Density"
  rrect17% 1x0.6 smd: 1(-1.375,0.95) 2(-1.375,0) 3(-1.375,-0.95) 4(1.375,-0.95) 5(1.375,0) 6(1.375,0.95)
  silkscreen extent -1.68,-1.55 0.5,1.55, body extent -1.42,-1.46 1.42,1.46, height 1.12
DPY0002A [mm] "X1SON-2"
  rrect57% 0.35x0.6 smd paste-0.5 mask-0.05: 1(-0.325,0) 2(0.325,0)
  rrect33% 0.3x0.5 on Bottom Paste: 1S(-0.35,0) 2S(0.35,0)
  body extent -0.5,-0.3 0.5,0.3, height 0.45
DQG0008A#1 [mm] "SMD, 8-Leads, Body 3.3x3.3mm, Pitch 0.65mm"
  rrect45% 0.75x0.44 smd paste-0.05 mask-0.05: 1(-1.525,0.975) 2(-1.525,0.325) 3(-1.525,-0.325) 4(-1.525,-0.975) 5(1.525,-0.975) 6(1.525,-0.325) 7(1.525,0.325) 8(1.525,0.975)
  rrect15% 0.676x1.125 on Top Paste: 9(-0.212,-0.663) 9(-0.212,0.662) 9(0.664,-0.663) 9(0.664,0.662)
  rrect6% 1.775x2.45 on Top Solder: 9(0.327,0)
  rrect8% 2.5x2.55 smd paste-1.5 mask-1.5: 9(0.65,0)
  rrect29% 0.5x0.34 on Top Solder: 9(1.175,-0.975) 9(1.175,-0.325) 9(1.175,0.325) 9(1.175,0.975)
  silkscreen extent -1.8,-1.8 1.8,1.8, body extent -1.65,-1.65 1.65,1.65, height 1.1
DQG0008A#2 [mm] "SMD, 8-Leads, Body 3.3x3.3mm, Pitch 0.65mm"
  rrect45% 0.75x0.44 smd paste-0.05 mask-0.05: 1(-1.525,0.975) 2(-1.525,0.325) 3(-1.525,-0.325) 4(-1.525,-0.975) 5(1.525,-0.975) 6(1.525,-0.325) 7(1.525,0.325) 8(1.525,0.975)
  rrect15% 0.676x1.125 on Bottom Paste: 9(-0.212,-0.663) 9(-0.212,0.662) 9(0.664,-0.663) 9(0.664,0.662)
  rrect6% 1.775x2.45 on Bottom Solder: 9(0.327,0)
  rrect8% 2.5x2.55 smd paste-1.5 mask-1.5: 9(0.65,0)
  rrect29% 0.5x0.34 on Bottom Solder: 9(1.175,-0.975) 9(1.175,-0.325) 9(1.175,0.325) 9(1.175,0.975)
  silkscreen extent -1.8,-1.8 1.8,1.8, body extent -1.65,-1.65 1.65,1.65, height 1.1
DRT0003A [mm] "SOTFL, 3-Leads, Body 1x1mm (inc leads), Pitch 0.35mm"
  rect 0.45x0.3 smd: 1(-0.575,0.35) 2(-0.575,-0.35) 3(0.575,0)
  silkscreen extent -0.03,-0.6 0.5,0.6, body extent -0.5,-0.5 0.5,0.5, height 0.5
DRZ0012A [mm] "SON, 12-Leads, Body 4x2.5mm, Pitch 0.4mm, Thermal Pad 1.95x2.45mm, TI Recommended"
  oval 0.6x0.2 smd: 1(-1.9,1) 2(-1.9,0.6) 3(-1.9,0.2) 4(-1.9,-0.2) 5(-1.9,-0.6) 6(-1.9,-1) 7(1.9,-1) 8(1.9,-0.6) 9(1.9,-0.2) 10(1.9,0.2) 11(1.9,0.6) 12(1.9,1)
  rect 2.45x1.95 smd paste-0.975: 13(0,0)
  Top Layer region: -1.225,-1.25 -1.225,1.25 -0.975,1.25 -0.975,0.975 0.975,0.975 0.975,1.25 1.225,1.25 1.225,-1.25 0.975,-1.25 0.975,-0.975 -0.975,-0.975 -0.975,-1.25
  silkscreen extent -2.1,-1.45 2,1.45, body extent -2.07,-1.3 2.07,1.3, height 1.01
HEADER_395021006 [mil] "Molex"
  rect 75x75 hole 47: 1(-345,0)
  round 75 hole 47: 2(-207,0) 3(-69,0) 4(69,0) 5(207,0) 6(345,0)
  silkscreen extent -366,55 -326,95, body extent -441,-310 441,50, height 270
Keystone5007 [mil] "Keystone Compact loops"
  round 87 hole 63: 1(0,0)
  silkscreen extent -70,-70 70,70, body extent -63,-63 62,63, height 225
Keystone5008 [mil] "Keystone Compact loops"
  round 87 hole 63: 1(0,0)
  silkscreen extent -70,-70 70,70, body extent -63,-63 62,63, height 225
Keystone5010 [mil] "Keystone Multipurpose loops"
  round 87 hole 63: 1(0,0)
  silkscreen extent -70,-70 70,70, body extent -63,-63 63,62, height 319
Keystone5013 [mil] "Keystone Multipurpose loops"
  round 87 hole 63: 1(0,0)
  silkscreen extent -70,-70 70,70, body extent -63,-63 63,62, height 319
Keystone_5019 [mm] "Test Point, Miniature, SMT"
  rect 3.8x2.03 smd: 1(0,0)
  silkscreen extent -2.31,-1.42 2.31,1.42, body extent -1.9,-1.02 1.9,1.02, height 2.29
LED_LTST-C190 [mm] "Lite-On"
  rect 0.8x0.8 smd: 1(-0.75,0) 2(0.75,0)
  silkscreen extent -1.1,-0.8 1.8,0.8, body extent -0.85,-0.45 0.85,0.45, height 0.9
LED_LTST-C190_Red [mm] "Lite-On"
  rect 0.8x0.8 smd: 1(-0.75,0) 2(0.75,0)
  silkscreen extent -1.1,-0.8 1.8,0.8, body extent -0.85,-0.45 0.85,0.45, height 0.9
Molex_0022284043 [mm] "Header, 2.54mm, 4x1, TH"
  rect 1.55x1.55 hole 1.02: 1(-3.81,0)
  round 1.55 hole 1.02: 2(-1.27,0) 3(1.27,0) 4(3.81,0)
  silkscreen extent -5.08,-1.24 5.08,1.5, body extent -5.08,-1.24 5.08,1.24, height 8.4
Molex_1051640001 [mm] "Receptacle, USB 2.0, Micro B, 5 Pos, 0.65mm Pitch, R/A, SMT"
  rrect22% 0.45x1.38 smd: 1(1.3,4.11) 2(0.65,4.11) 3(0,4.11) 4(-0.65,4.11) 5(-1.3,4.11)
  rrect7% 1.475x2.1 smd: 6(-2.462,3.75) 11(2.462,3.75)
  rrect100% 1.4x2.1 hole 0.6 slot 1.3 at 90 deg: 7(-3.95,1.45) 10(3.95,1.45)
  rrect7% 1.375x1.9 smd: 8(-0.937,1.45) 9(0.937,1.45)
  silkscreen extent 1.2,5.1 1.4,5.4, body extent -4.1,-0.7 4.1,4.47, height 2.45
Net-Tie_10mil [mil] "10mil net tie, no solder mask opening, no solder paste"
  rect 10x10 smd paste-5 mask-5: 1(-10,0) 2(10,0)
  Top Layer region: -6,5 6,5 6,-5 -6,-5
RGE0024H [mm] "QFN, 24-Leads, Body 4x4mm, Pitch 0.5mm, Thermal Pad 2.7x2.7mm, TI Recommended"
  rrect42% 0.6x0.24 smd: 1(-1.9,1.25) 2(-1.9,0.75) 3(-1.9,0.25) 4(-1.9,-0.25) 5(-1.9,-0.75) 6(-1.9,-1.25) 13(1.9,-1.25) 14(1.9,-0.75) 15(1.9,-0.25) 16(1.9,0.25) 17(1.9,0.75) 18(1.9,1.25)
  rrect42% 0.24x0.6 smd: 7(-1.25,-1.9) 8(-0.75,-1.9) 9(-0.25,-1.9) 10(0.25,-1.9) 11(0.75,-1.9) 12(1.25,-1.9) 19(1.25,1.9) 20(0.75,1.9) 21(0.25,1.9) 22(-0.25,1.9) 23(-0.75,1.9) 24(-1.25,1.9)
  rrect8% 1.19x1.19 on Top Paste: 25(-0.695,-0.695) 25(-0.695,0.695) 25(0.695,-0.695) 25(0.695,0.695)
  rrect4% 2.7x2.7 smd paste-1.35: 25(0,0)
  silkscreen extent -2.22,-2.22 2.22,2.22, body extent -2.07,-2.07 2.07,2.07, height 1.01
RGE0024H_NV [mm] "QFN, 24-Leads, Body 4x4mm, Pitch 0.5mm, Thermal Pad 2.7x2.7mm, TI Recommended"
  rrect42% 0.6x0.24 smd: 1(-1.9,1.25) 2(-1.9,0.75) 3(-1.9,0.25) 4(-1.9,-0.25) 5(-1.9,-0.75) 6(-1.9,-1.25) 13(1.9,-1.25) 14(1.9,-0.75) 15(1.9,-0.25) 16(1.9,0.25) 17(1.9,0.75) 18(1.9,1.25)
  rrect42% 0.24x0.6 smd: 7(-1.25,-1.9) 8(-0.75,-1.9) 9(-0.25,-1.9) 10(0.25,-1.9) 11(0.75,-1.9) 12(1.25,-1.9) 19(1.25,1.9) 20(0.75,1.9) 21(0.25,1.9) 22(-0.25,1.9) 23(-0.75,1.9) 24(-1.25,1.9)
  rrect8% 1.19x1.19 on Top Paste: 25(-0.695,-0.695) 25(-0.695,0.695) 25(0.695,-0.695) 25(0.695,0.695)
  rrect4% 2.7x2.7 smd paste-1.35: 25(0,0)
  silkscreen extent -2.22,-2.22 2.22,2.22, body extent -2.07,-2.07 2.07,2.07, height 1.01
RWB0012A [mm] "QFN, 12-Leads, Body 1.6x1.6mm, Pitch 0.4mm"
  rrect57% 0.7x0.2 smd paste-0.1: 1(-0.65,0.2) 2(-0.65,-0.2) 7(0.65,-0.2) 8(0.65,0.2)
  rrect57% 0.2x0.5 smd: 3(-0.6,-0.75) 4(-0.2,-0.75) 5(0.2,-0.75) 6(0.6,-0.75) 9(0.6,0.75) 10(0.2,0.75) 11(-0.2,0.75) 12(-0.6,0.75)
  silkscreen extent -0.92,-0.91 0.92,0.91, body extent -0.8,-0.8 0.8,0.8, height 0.4
SMA [mm] "Molded Diode, 2-Leads, Body 4.3x2.6mm, IPC Medium Density, based on OnSemi component dimensions and land pattern"
  rect 2x2 smd: 1(-2,0) 2(2,0)
  silkscreen extent -3.66,-1.57 2.79,1.57, body extent -2.6,-1.3 2.6,1.3, height 2.42
SNT-100-BK-G [mil] "Samtec STEP model"
  round 1 on Mech3: 0(0,0)
  body extent -100,-50 100,50, height 344
SOD-123W [mm] "NXP recommended land pattern"
  rect 1.2x1.2 smd paste-0.05: 1(-1.4,0) 2(1.4,0)
  silkscreen extent -2.64,-1.14 1.68,1.14, body extent -1.85,-0.95 1.85,0.95, height 1.1
SOD-323 [mm] "NXP recommended land pattern"
  rect 0.6x0.6 smd paste-0.05: 1(-1.1,0) 2(1.1,0)
  silkscreen extent -2.06,-0.86 1.53,0.86, body extent -1.3,-0.67 1.3,0.68, height 1.1
SOT-23 [mm] "SOT23, 3-Leads, Body 2.9x1.3mm, Pitch 0.95mm, Lead Span 2.5mm, IPC Medium Density"
  rrect50% 1x0.6 smd: 1(-1.2,0.95) 2(-1.2,-0.95) 3(1.2,0)
  silkscreen extent -1.63,-1.5 0.7,1.5, body extent -1.16,-1.45 1.21,1.45, height 1
SOT-563 [mm] "Wurth recommended land pattern 82400152.pdf"
  rrect33% 0.5x0.3 smd mask+0.051: 1(-0.7,0.508) 2(-0.7,0) 3(-0.7,-0.508) 4(0.7,-0.508) 5(0.7,0) 6(0.7,0.508)
  silkscreen extent -0.8,-1 0.4,1, body extent -0.85,-0.85 0.85,0.85, height 0.6
SPARK_GAP2 [mil] "Copied from PADS legacy libraries."
  rect 10x20 smd: 1(0,20) 2(0,-10)
  Top Layer region: -15,30 -25,30 -25,-30 25,-30 25,30 15,30 15,-20 -15,-20 -15,30
Sullins_xPxC071LFBN [mm] "Receptacle, 2.54mm, 7x1, TH"
  rect 1.55x1.55 hole 1.02: 1(-7.62,0)
  round 1.55 hole 1.02: 2(-5.08,0) 3(-2.54,0) 4(0,0) 5(2.54,0) 6(5.08,0) 7(7.62,0)
  silkscreen extent -9.14,-1.27 9.14,1.8, body extent -9.14,-1.27 9.14,1.27, height 8.5
SW_B3SL-1002P [mm] "Omron"
  rect 2.75x1 smd: 1(-2.875,2) 2(2.875,2) 3(-2.875,-2) 4(2.875,-2)
  silkscreen extent -3.1,-3.25 3.1,3.25, body extent -3.2,-3.35 3.2,3.35, height 3.4
TERM_BLK_ED555-4DS [mm]
  rect 2.54x2.54 hole 1.27: 1(0,0)
  round 2.54 hole 1.27: 2(3.5,0) 3(7,0) 4(10.5,0)
  silkscreen extent -2.36,-4.09 12.25,2.67, body extent -1.75,-3.8 12.25,2.7, height 8.2
WE-MAPI_3020 [mm] "SMD, 2-Leads, Body 3.2x3.2mm"
  rect 1.3x3.4 smd: 1(-1.05,0) 2(1.05,0)
  silkscreen extent -0.1,-1.6 0.1,1.6, body extent -1.6,-1.6 1.6,1.6, height 2
WSLP1206-001 [mm] "Vishay"
  rect 1.57x1.78 smd: 1(-1.165,0) 2(1.165,0)
  silkscreen extent -0.2,-1.02 0.2,1.05, body extent -1.73,-0.93 1.73,0.93, height 0.89
Wurth_632_723_300_011 [mm] "Connector, Receptacle, USB Type C, R/A"
  rect 0.3x1.2 smd: A1(-2.75,10.58) A2(-2.25,10.58) A3(-1.75,10.58) A4(-1.25,10.58) A5(-0.75,10.58) A6(-0.25,10.58) A7(0.25,10.58) A8(0.75,10.58) A9(1.25,10.58) A10(1.75,10.58) A11(2.25,10.58) A12(2.75,10.58)
  round 0.55 hole 0.4: B1(2.8,9.32) B2(2.4,8.62) B3(1.6,8.62) B4(1.2,9.32) B5(0.8,8.62) B6(0.4,9.32) B7(-0.4,9.32) B8(-0.8,8.62) B9(-1.2,9.32) B10(-1.6,8.62) B11(-2.4,8.62) B12(-2.8,9.32) M1(2,9.32) M2(-2,9.32)
  rrect100% 1x1.6 hole 0.6 slot 1.2 at 90 deg: S1(-4.27,8.18) S2(-4.27,3.45) S3(4.27,3.45) S4(4.27,8.18)
  silkscreen extent -4.37,0.15 4.37,10.36, body extent -4.37,-0.96 4.37,10.83, height 3.07

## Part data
BT1 BT2: library part CMP-0003634-1, "Battery Holder, Plastic, 18650, TH", Manufacturer=Keystone, Supplier Part Number 1=36-1043-ND
C1 C2: library part CMP-0008305-2, "CAP, CERM, 22 uF, 25 V, +/- 20%, X5R, 0805", Cap_Case=0805, Manufacturer=MuRata, Supplier Part Number 1=490-10749-1-ND, TempCo=X5R, Tolerance_%=20%, Value1=Unknown, Value2=25V, ValueDisplayed=22uF
C3 C9: library part CMP-0083856-1, "CAP, CERM, 1 µF, 25 V,+/- 10%, X7R, 0603", Cap_Case=0603, Manufacturer=TDK, TempCo=X7R, Tolerance_%=10%, Value2=25V, ValueDisplayed=1µF
C4 C5 C7: library part CMP-0007007-5, "CAP, CERM, 10 uF, 25 V, +/- 20%, X5R, 0603", Cap_Case=0603, Manufacturer=TDK, Supplier Part Number 1=445-9015-1-ND, TempCo=X5R, Tolerance_%=20%, Value1="0.004639 ohm", Value2=25V, ValueDisplayed=10uF
C6: library part CMP-0006669-2, "CAP, CERM, 0.047 uF, 25 V, +/- 10%, X7R, 0402", Cap_Case=0402, Manufacturer=MuRata, Supplier Part Number 1=490-3254-1-ND, TempCo=X7R, Tolerance_%=10%, Value1=Unknown, Value2=25V, ValueDisplayed=0.047uF
C8 C13 C18: library part CMP-0006268-2, "CAP, CERM, 4.7 uF, 10 V, +/- 10%, X5R, 0402", Cap_Case=0402_065, Manufacturer=TDK, Supplier Part Number 1=445-13820-1-ND, TempCo=X5R, Tolerance_%=10%, Value1="0.003417 ohm", Value2=10V, ValueDisplayed=4.7uF
C10 C12 C17 C24: library part CMP-0006347-2, "CAP, CERM, 1 uF, 16 V, +/- 10%, X5R, 0402", Cap_Case=0402, Manufacturer="Taiyo Yuden", Supplier Part Number 1=587-3709-2-ND, TempCo=X5R, Tolerance_%=10%, Value1=Unknown, Value2=16V, ValueDisplayed=1uF
C11 C15 C16 C19 C26 C27: library part CMP-0006659-2, "CAP, CERM, 0.1 uF, 25 V, +/- 10%, X7R, 0402", Cap_Case=0402, Manufacturer=MuRata, Supplier Part Number 1=490-10698-1-ND, TempCo=X7R, Tolerance_%=10%, Value1=Unknown, Value2=25V, ValueDisplayed=0.1uF
C14 C29 C30 C31 C32: library part CMP-0006658-2, "CAP, CERM, 0.01 uF, 25 V, +/- 10%, X7R, 0402", Cap_Case=0402, Manufacturer=MuRata, Supplier Part Number 1=490-1312-1-ND, TempCo=X7R, Tolerance_%=10%, Value1=Unknown, Value2=25V, ValueDisplayed=0.01uF
C20: library part CMP-0006606-2, "CAP, CERM, 1000 pF, 25 V, +/- 10%, X5R, 0402", Cap_Case=0402, Manufacturer=MuRata, Supplier Part Number 1=GRM155R61E102KA01D-ND, TempCo=X5R, Tolerance_%=10%, Value1=Unknown, Value2=25V, ValueDisplayed=1000pF
C21 C22 C23 C25: "CAP, CERM, 0.1 µF, 50 V, +/- 10%, X7R, 0402", Cap_Case=0402, Manufacturer=TDK, Supplier Part Number 1=445-5932-1-ND, TempCo=X7R, Tolerance_%=10, Value1="0.039064 ohm", Value2=50V, ValueDisplayed=0.1µF
C28: library part CMP-0006594-2, "CAP, CERM, 2.2 uF, 16 V, +/- 10%, X5R, 0402", Cap_Case=0402, Manufacturer=MuRata, Supplier Part Number 1=490-10695-1-ND, TempCo=X5R, Tolerance_%=10%, Value1=Unknown, Value2=16V, ValueDisplayed=2.2uF
D1 D3 D4 D5: library part CMP-0005819-4, "Diode, TVS, Uni, 13 V, 21.5 Vc, SOD-123W", Manufacturer="NXP Semiconductor"
D2: library part CMP-0028347-2, "Diode, Schottky, 20 V, 3 A, SMA", Manufacturer="Diodes Inc.", Value1=3A, Value2=0.5V
D6: library part CMP-0002827-3, "LED, Green, SMD", Color=green, Manufacturer=Lite-On, Power_TotalModule=100mW, Value1=0.1W, Value2=2.1V
D7: library part CMP-0002842-2, "LED, Red, SMD", Color=red, Manufacturer=Lite-On, Power_TotalModule=62.5mW, Value1=0.0625W, Value2=2V
D8: library part CMP-0002826-2, "LED, Orange, SMD", Color=orange, Manufacturer=Lite-On, Power_TotalModule=75mW, Supplier Part Number 1=160-1434-1-ND, Value1=0.075W, Value2=2V
D9: library part CMP-0082069-2, "Diode, Switching, 75 V, 0.15 A, SOD-323", Manufacturer="Micro Commercial Components", Value1=0.15A, Value2=1V
D10: library part CMP-0005833-4, "Diode, Zener, 15 V, 200 mW, SOD-323", Manufacturer="Diodes Inc.", Power_W=200mW, Value1=0.2W
E1 E2 E3: library part SparkGap, "Spark Gap", Alternate Manufacturer=-
J1 J14: library part CMP-0074917-1, "Terminal Block, 3.5mm Pitch, 4x1, TH", Color=Grey, Current_A=6A, Manufacturer="On-Shore Technology", Supplier Part Number 1=ED1516-ND, Voltage_V=150V
J2: library part CMP-0055311-1, "Receptacle, USB 2.0, Micro B, 5 Position, R/A, SMT", Color=Black, Current_A=1.8A, Manufacturer=Molex, Supplier Part Number 1=WM11263CT-ND, Voltage_V=30V
J4: library part CMP-0080891-1, "Connector, Receptacle, USB Type C, R/A", Color=Black, Current_A=3A, Manufacturer="Wurth Elektronik", Supplier Part Number 1=732-9618-1-ND, Voltage_V=5V
J5: library part CMP-0002339-2, "Header, 100mil, 7x2, Tin, TH", Color=Black, Current_A=3A, Manufacturer="Sullins Connector Solutions", Supplier Part Number 1=S2012E-07-ND, Voltage_V=1.8kV
J6: library part CMP-0054674-1, "Receptacle, 2.54mm, 7x1, Gold, TH", Color=Black, Current_A=3A, Manufacturer="Sullins Connector Solutions", Supplier Part Number 1=S7040-ND, Voltage_V=250V
J7: library part CMP-0055331-1, "Header, 2.54mm, 4x1, Tin, TH", Color=Black, Current_A=4A, Manufacturer=Molex, Supplier Part Number 1=WM50016-04-ND, Voltage_V=250V
J8 J10 JP1 JP2: library part CMP-0002338-1, "Header, 100mil, 3x1, Tin, TH", Color=Black, Current_A=3A, Manufacturer="Sullins Connector Solutions", Supplier Part Number 1=S1012E-03-ND, Voltage_V=1.8kV
J9 J15: library part CMP-0055187-1, "Header (friction lock), 100mil, 4x1, R/A, TH", Manufacturer=Molex, Supplier Part Number 1=WM4302-ND
J11 J12: library part CMP-0055336-1, "Terminal Block Header, 3.5mm 6x1, Tin, R/A, TH", Manufacturer=Molex, Supplier Part Number 1=WM7774-ND
L1: library part CMP-0064157-1, "Inductor, Shielded, 1 uH, 4 A, 0.032 ohm, SMD", Case/Package=SMD/SMT, Case Code (Imperial)=1212, Case Code (Metric)=3030, Current Rating=4A, Manufacturer="Wurth Electronics", Max Operating Temperature=125°C, Min Operating Temperature=-40°C, Package Quantity=1000, PartNumber=74438336010, Saturation Current=5A, Self Resonant Frequency=67MHz, Supplier Part Number 1=732-5693-1-ND, Test Frequency=100kHz, Tolerance_%=20%, ValueDisplayed=1uH
NT1: "Single point connection between nets."
Q1: library part CMP-0000223-1, "MOSFET, 2-CH, N-CH, 20 V, 0.54 A, SOT-563", Alternate Manufacturer=None, Manufacturer="ON Semiconductor", Supplier Part Number 1=NTZD3154NT1GOSCT-ND, Value1=0, Value2="1.5 nC"
Q2 Q3 Q5: library part CMP-0000257-1, "MOSFET, N-CH, 25 V, 60 A, DQG0008A (VSON-CLIP-8)", Alternate Manufacturer=None, Manufacturer="Texas Instruments", Supplier Part Number 1=296-30138-1-ND, Value1=0.004, Value2="6.2 nC"
Q4: library part CMP-0000773-1, "MOSFET, N-CH, 60 V, 0.3 A, SOT-23", Alternate Manufacturer=None, Manufacturer=Vishay-Siliconix, Supplier Part Number 1=2N7002K-T1-E3CT-ND, Value2="0.4 nC"
R1 R4: library part CMP-0017256-2, "RES, 0.01, 1%, 0.5 W, 1206", Manufacturer="Stackpole Electronics Inc", Power_W=500mW, Supplier Part Number 1=CSR1206FK10L0CT-ND, TempCo="100 ppm/C", Tolerance_%=1%, Value2=0.5W, Value_Code=R010, ValueDisplayed=0.01
R2: library part CMP-0026326-2, "RES, 392, 1%, 0.063 W, AEC-Q200 Grade 0, 0402", Manufacturer=Vishay-Dale, Power_W=63mW, Supplier Part Number 1=541-392LCT-ND, TempCo="100 ppm/C", Tolerance_%=1%, Value2=0.063W, Value_Code=392R, ValueDisplayed=392
R3: library part CMP-0026822-3, "RES, 0, 5%, 0.063 W, AEC-Q200 Grade 0, 0402", Manufacturer=Vishay-Dale, Power_W=63mW, Supplier Part Number 1=541-0.0JCT-ND, TempCo="200 ppm/C", Tolerance_%=5%, Value2=0.063W, Value_Code=0000, ValueDisplayed=0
